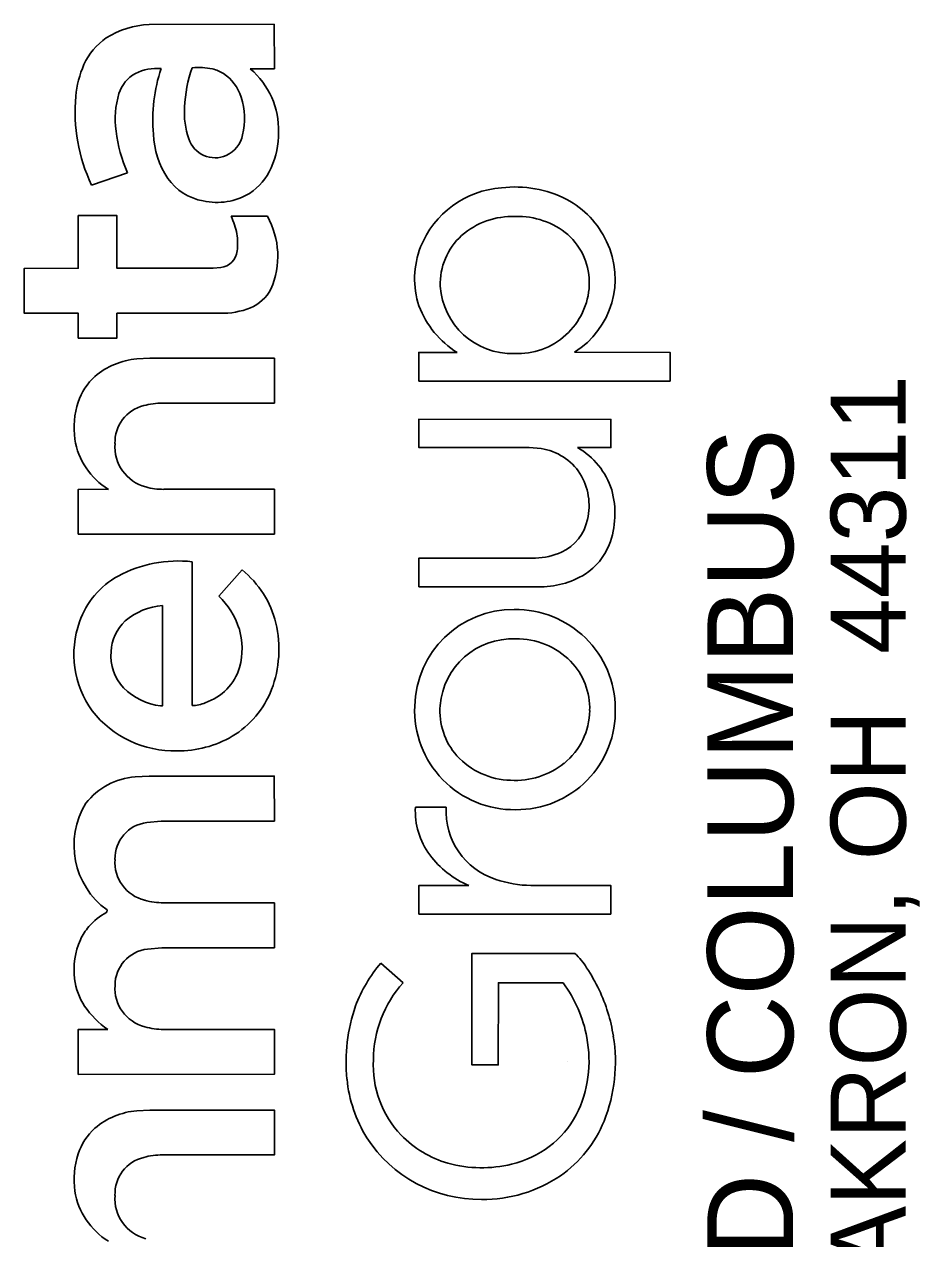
# Model space of a CAD drawing. Extents: x 0 to 34, y 0 to 22.
# Drawn here: x 32.39 to 32.984, y 3.382 to 4.189 of the extents above; entities that cross this region are included whole.
import ezdxf

# ---------------------------------------------------------------- set-up
doc = ezdxf.new("R2010")
doc.units = 0
doc.layers.add('SH_Data', color=7, linetype='Continuous')

msp = doc.modelspace()

# ---------------------------------------------------------------- linework, layer by layer
at = {"layer": 'SH_Data'}
for p, q in [((32.47265, 4.18899), (32.55553, 4.18918)), ((32.55553, 4.18918), (32.55571, 4.15956)), ((32.55571, 4.15956), (32.53971, 4.15956)), ((32.45818, 4.09045), (32.43431, 4.08233)), ((32.42542, 4.02705), (32.42548, 4.06209)), ((32.42548, 4.06209), (32.45108, 4.06209)), ((32.45108, 4.06209), (32.45117, 4.02705)), ((32.52695, 4.06159), (32.5511, 4.06159)), ((32.38964, 4.02701), (32.42542, 4.02705)), ((32.38964, 3.99719), (32.38964, 4.02701)), ((32.45117, 4.02705), (32.51498, 4.02705)), ((32.51498, 4.02705), (32.52005, 4.02749)), ((32.42542, 3.99717), (32.38964, 3.99719)), ((32.42542, 3.98067), (32.42542, 3.99717)), ((32.51969, 3.99718), (32.45108, 3.99715)), ((32.45108, 3.99715), (32.45108, 3.98066)), ((32.45108, 3.98066), (32.42542, 3.98067)), ((32.65152, 3.97113), (32.67709, 3.97115)), ((32.65152, 3.95215), (32.65152, 3.97113)), ((32.75491, 3.97132), (32.81858, 3.97108)), ((32.81858, 3.97108), (32.81843, 3.95215)), ((32.46439, 3.96686), (32.47289, 3.96732)), ((32.47289, 3.96732), (32.55571, 3.96732)), ((32.55571, 3.96732), (32.55571, 3.93753)), ((32.81843, 3.95215), (32.65152, 3.95215)), ((32.55571, 3.93753), (32.4814, 3.93746)), ((32.65152, 3.90801), (32.65153, 3.92672)), ((32.65153, 3.92672), (32.7791, 3.92664)), ((32.7791, 3.92664), (32.77908, 3.90796)), ((32.7249, 3.90796), (32.65152, 3.90801)), ((32.7328, 3.90727), (32.7249, 3.90796)), ((32.77908, 3.90796), (32.75689, 3.90796)), ((32.42542, 3.88016), (32.44552, 3.88021)), ((32.42542, 3.85035), (32.42542, 3.88016)), ((32.48222, 3.88021), (32.55569, 3.88021)), ((32.55569, 3.88021), (32.55571, 3.85045)), ((32.55571, 3.85045), (32.42542, 3.85035)), ((32.65154, 3.83443), (32.72905, 3.8345)), ((32.65165, 3.81543), (32.65154, 3.83443)), ((32.50108, 3.83209), (32.50118, 3.73657)), ((32.51882, 3.80927), (32.53422, 3.82662)), ((32.73073, 3.81543), (32.65165, 3.81543)), ((32.48144, 3.73644), (32.48144, 3.80296)), ((32.48016, 3.73628), (32.48144, 3.73644)), ((32.46329, 3.68915), (32.47259, 3.68968)), ((32.47259, 3.68968), (32.55557, 3.68968)), ((32.55557, 3.68968), (32.55571, 3.65982)), ((32.64932, 3.66907), (32.66978, 3.66907)), ((32.48058, 3.65981), (32.47102, 3.65881)), ((32.55571, 3.65982), (32.48058, 3.65981)), ((32.65152, 3.61699), (32.68476, 3.617)), ((32.65152, 3.598), (32.65152, 3.61699)), ((32.72605, 3.61703), (32.7791, 3.61696)), ((32.7791, 3.61696), (32.77903, 3.598)), ((32.44443, 3.59922), (32.44455, 3.60072)), ((32.48218, 3.60553), (32.55571, 3.60548)), ((32.55571, 3.60548), (32.55571, 3.57568)), ((32.77903, 3.598), (32.65152, 3.598)), ((32.4809, 3.57567), (32.47143, 3.57474)), ((32.55571, 3.57568), (32.4809, 3.57567)), ((32.6868, 3.57185), (32.75516, 3.57192)), ((32.6868, 3.49778), (32.6868, 3.57185)), ((32.62636, 3.56548), (32.64114, 3.55241)), ((32.70448, 3.55241), (32.70432, 3.49775)), ((32.74737, 3.55227), (32.70448, 3.55241)), ((32.42542, 3.49152), (32.42545, 3.52138)), ((32.42545, 3.52138), (32.44515, 3.52138)), ((32.48206, 3.52138), (32.55571, 3.52136)), ((32.55571, 3.52136), (32.55571, 3.49156)), ((32.70432, 3.49775), (32.6868, 3.49778)), ((32.75, 3.5), (32.75, 3.5)), ((32.55571, 3.49156), (32.42542, 3.49152)), ((32.46439, 3.46736), (32.47289, 3.46783)), ((32.47289, 3.46783), (32.55571, 3.46783)), ((32.55571, 3.46783), (32.55571, 3.43804)), ((32.55571, 3.43804), (32.4814, 3.43796))]:
    msp.add_line(p, q, dxfattribs=at)
for points in [[(32.47265, 4.18899), (32.55553, 4.18918), (32.55571, 4.15956)], [(32.55571, 4.15956), (32.53971, 4.15956)], [(32.45818, 4.09045), (32.43431, 4.08233)], [(32.51969, 3.99718), (32.45108, 3.99715), (32.45108, 3.98066), (32.42542, 3.98067), (32.42542, 3.99717), (32.38964, 3.99719), (32.38964, 4.02701), (32.42542, 4.02705), (32.42548, 4.06209), (32.45108, 4.06209), (32.45117, 4.02705), (32.51498, 4.02705), (32.52005, 4.02749)], [(32.52695, 4.06159), (32.5511, 4.06159)], [(32.75491, 3.97132), (32.81858, 3.97108), (32.81843, 3.95215), (32.65152, 3.95215)], [(32.65152, 3.95215), (32.65152, 3.97113), (32.67709, 3.97115)], [(32.46439, 3.96686), (32.47289, 3.96732), (32.55571, 3.96732), (32.55571, 3.93753), (32.4814, 3.93746)], [(32.7328, 3.90727), (32.7249, 3.90796), (32.65152, 3.90801), (32.65153, 3.92672), (32.7791, 3.92664), (32.77908, 3.90796), (32.75689, 3.90796)], [(32.42542, 3.85035), (32.42542, 3.88016), (32.44552, 3.88021)], [(32.48222, 3.88021), (32.55569, 3.88021), (32.55571, 3.85045), (32.42542, 3.85035)], [(32.73073, 3.81543), (32.65165, 3.81543), (32.65154, 3.83443), (32.72905, 3.8345)], [(32.50108, 3.83209), (32.50118, 3.73657)], [(32.51882, 3.80927), (32.53422, 3.82662)], [(32.48016, 3.73628), (32.48144, 3.73644), (32.48144, 3.80296)], [(32.46329, 3.68915), (32.47259, 3.68968), (32.55557, 3.68968), (32.55571, 3.65982), (32.48058, 3.65981), (32.47102, 3.65881)], [(32.64932, 3.66907), (32.66978, 3.66907)], [(32.72605, 3.61703), (32.7791, 3.61696), (32.77903, 3.598), (32.65152, 3.598)], [(32.65152, 3.598), (32.65152, 3.61699), (32.68476, 3.617)], [(32.44443, 3.59922), (32.44455, 3.60072)], [(32.48218, 3.60553), (32.55571, 3.60548), (32.55571, 3.57568), (32.4809, 3.57567), (32.47143, 3.57474)], [(32.74737, 3.55227), (32.70448, 3.55241), (32.70432, 3.49775), (32.6868, 3.49778), (32.6868, 3.57185), (32.75516, 3.57192)], [(32.62636, 3.56548), (32.64114, 3.55241)], [(32.42542, 3.49152), (32.42545, 3.52138), (32.44515, 3.52138)], [(32.48206, 3.52138), (32.55571, 3.52136), (32.55571, 3.49156), (32.42542, 3.49152)], [(32.46439, 3.46736), (32.47289, 3.46783), (32.55571, 3.46783), (32.55571, 3.43804), (32.4814, 3.43796)]]:
    msp.add_lwpolyline(points, dxfattribs=at)
for centre, radius, start, end in [((32.47452, 4.13256), 0.05646, 91.89422, 122.63175), ((32.47452, 4.13256), 0.05646, 91.89422, 122.63175), ((32.46847, 4.14467), 0.04302, 124.53704, 155.65938), ((32.46847, 4.14467), 0.04302, 124.53704, 155.65938), ((32.48824, 4.13612), 0.06457, 155.9764, 175.31491), ((32.48824, 4.13612), 0.06457, 155.9764, 175.31491), ((32.47525, 4.1356), 0.024, 119.42515, 161.66285), ((32.47525, 4.1356), 0.024, 119.42515, 161.66285), ((32.47786, 4.12778), 0.03213, 85.38017, 116.62224), ((32.47786, 4.12778), 0.03213, 85.38017, 116.62224), ((32.58787, 4.12508), 0.1129, 162.08213, 184.52847), ((32.58787, 4.12508), 0.1129, 162.08213, 184.52847), ((32.58013, 4.13131), 0.08411, 159.83657, 178.03621), ((32.58013, 4.13131), 0.08411, 159.83657, 178.03621), ((32.50509, 4.10743), 0.05302, 79.66963, 94.23216), ((32.50509, 4.10743), 0.05302, 79.66963, 94.23216), ((32.50892, 4.13643), 0.02384, 56.89129, 76.21489), ((32.50892, 4.13643), 0.02384, 56.89129, 76.21489), ((32.5052, 4.13184), 0.02973, 17.59837, 55.72819), ((32.5052, 4.13184), 0.02973, 17.59837, 55.72819), ((32.50551, 4.11914), 0.05295, 358.07459, 49.76196), ((32.50551, 4.11914), 0.05295, 358.07459, 49.76196), ((32.53639, 4.13078), 0.113, 174.61011, 205.38987), ((32.53639, 4.13078), 0.113, 174.61011, 205.38987), ((32.50758, 4.12645), 0.05758, 163.13694, 188.16749), ((32.50758, 4.12645), 0.05758, 163.13694, 188.16749), ((32.4916, 4.1264), 0.04435, 345.94084, 18.99188), ((32.4916, 4.1264), 0.04435, 345.94084, 18.99188), ((32.54655, 4.1303), 0.05063, 175.59026, 199.88569), ((32.54655, 4.1303), 0.05063, 175.59026, 199.88569), ((32.54725, 4.12973), 0.09735, 186.75982, 203.79807), ((32.54725, 4.12973), 0.09735, 186.75982, 203.79807), ((32.53279, 4.11874), 0.05752, 182.56764, 213.71437), ((32.53279, 4.11874), 0.05752, 182.56764, 213.71437), ((32.51521, 4.11994), 0.01989, 295.28829, 347.46387), ((32.51521, 4.11994), 0.01989, 295.28829, 347.46387), ((32.50187, 4.11678), 0.05657, 336.01604, 0.59505), ((32.50187, 4.11678), 0.05657, 336.01604, 0.59505), ((32.51642, 4.11886), 0.01841, 198.28436, 293.30806), ((32.51642, 4.11886), 0.01841, 198.28436, 293.30806), ((32.51752, 4.10969), 0.03938, 303.44357, 336.18), ((32.51752, 4.10969), 0.03938, 303.44357, 336.18), ((32.51487, 4.10782), 0.03656, 215.06685, 259.81327), ((32.51487, 4.10782), 0.03656, 215.06685, 259.81327), ((32.51753, 4.1131), 0.04227, 257.52557, 300.88195), ((32.51753, 4.1131), 0.04227, 257.52557, 300.88195), ((32.71081, 4.01825), 0.06243, 93.98662, 158.31194), ((32.71081, 4.01825), 0.06243, 93.98662, 158.31194), ((32.71557, 4.0065), 0.07459, 62.68889, 97.01346), ((32.71557, 4.0065), 0.07459, 62.68889, 97.01346), ((32.72123, 4.01914), 0.06076, 25.06574, 61.96022), ((32.72123, 4.01914), 0.06076, 25.06574, 61.96022), ((32.48625, 4.04199), 0.04518, 10.15449, 25.72303), ((32.48625, 4.04199), 0.04518, 10.15449, 25.72303), ((32.50302, 4.03506), 0.05491, 336.58903, 28.89913), ((32.50302, 4.03506), 0.05491, 336.58903, 28.89913), ((32.71379, 4.01017), 0.05134, 87.89653, 131.18123), ((32.71379, 4.01017), 0.05134, 87.89653, 131.18123), ((32.7175, 4.01023), 0.05127, 49.90886, 92.03625), ((32.7175, 4.01023), 0.05127, 49.90886, 92.03625), ((32.49573, 4.04365), 0.03556, 351.91398, 10.20594), ((32.49573, 4.04365), 0.03556, 351.91398, 10.20594), ((32.7092, 4.01674), 0.04338, 132.32887, 182.09489), ((32.7092, 4.01674), 0.04338, 132.32887, 182.09489), ((32.72154, 4.01733), 0.04327, 358.04871, 47.94467), ((32.72154, 4.01733), 0.04327, 358.04871, 47.94467), ((32.7245, 4.02004), 0.05743, 301.97764, 25.64176), ((32.7245, 4.02004), 0.05743, 301.97764, 25.64176), ((32.51837, 4.04001), 0.01263, 277.61423, 353.79181), ((32.51837, 4.04001), 0.01263, 277.61423, 353.79181), ((32.70695, 4.02016), 0.05815, 158.65601, 198.17101), ((32.70695, 4.02016), 0.05815, 158.65601, 198.17101), ((32.52913, 4.02612), 0.02749, 292.68889, 332.05977), ((32.52913, 4.02612), 0.02749, 292.68889, 332.05977), ((32.71352, 4.01815), 0.04776, 183.59741, 271.7045), ((32.71352, 4.01815), 0.04776, 183.59741, 271.7045), ((32.71717, 4.01801), 0.04766, 267.31494, 357.4019), ((32.71717, 4.01801), 0.04766, 267.31494, 357.4019), ((32.7103, 4.02433), 0.0627, 200.83985, 238.01619), ((32.7103, 4.02433), 0.0627, 200.83985, 238.01619), ((32.52088, 4.04856), 0.05139, 268.67266, 291.52354), ((32.52088, 4.04856), 0.05139, 268.67266, 291.52354), ((32.46871, 3.91716), 0.04988, 94.97056, 130.22484), ((32.46871, 3.91716), 0.04988, 94.97056, 130.22484), ((32.46348, 3.92551), 0.04016, 132.22383, 161.68229), ((32.46348, 3.92551), 0.04016, 132.22383, 161.68229), ((32.47872, 3.92108), 0.05602, 162.27398, 187.79173), ((32.47872, 3.92108), 0.05602, 162.27398, 187.79173), ((32.48108, 3.89145), 0.04601, 89.60515, 105.33026), ((32.48108, 3.89145), 0.04601, 89.60515, 105.33026), ((32.47482, 3.91155), 0.02498, 103.68683, 182.21395), ((32.47482, 3.91155), 0.02498, 103.68683, 182.21395), ((32.47027, 3.9209), 0.04763, 188.96462, 238.69865), ((32.47027, 3.9209), 0.04763, 188.96462, 238.69865), ((32.47735, 3.90846), 0.02757, 175.58441, 255.13816), ((32.47735, 3.90846), 0.02757, 175.58441, 255.13816), ((32.72711, 3.86998), 0.03772, 33.50082, 81.32954), ((32.72711, 3.86998), 0.03772, 33.50082, 81.32954), ((32.73239, 3.86485), 0.04959, 17.62209, 60.38974), ((32.73239, 3.86485), 0.04959, 17.62209, 60.38974), ((32.72414, 3.8695), 0.04048, 346.56179, 31.75389), ((32.72414, 3.8695), 0.04048, 346.56179, 31.75389), ((32.48183, 3.92235), 0.04215, 254.08913, 270.52838), ((32.48183, 3.92235), 0.04215, 254.08913, 270.52838), ((32.72343, 3.86415), 0.05838, 339.16197, 15.61485), ((32.72343, 3.86415), 0.05838, 339.16197, 15.61485), ((32.73371, 3.86616), 0.03042, 294.63214, 348.48625), ((32.73371, 3.86616), 0.03042, 294.63214, 348.48625), ((32.739, 3.85901), 0.04201, 303.10391, 338.15613), ((32.739, 3.85901), 0.04201, 303.10391, 338.15613), ((32.49176, 3.74874), 0.08387, 83.62118, 118.28448), ((32.49176, 3.74874), 0.08387, 83.62118, 118.28448), ((32.72747, 3.88081), 0.04633, 271.95199, 294.08943), ((32.72747, 3.88081), 0.04633, 271.95199, 294.08943), ((32.49399, 3.7763), 0.06443, 13.53275, 51.36266), ((32.49399, 3.7763), 0.06443, 13.53275, 51.36266), ((32.47894, 3.77368), 0.05583, 118.82935, 160.62242), ((32.47894, 3.77368), 0.05583, 118.82935, 160.62242), ((32.7321, 3.87256), 0.05715, 268.62699, 301.47779), ((32.7321, 3.87256), 0.05715, 268.62699, 301.47779), ((32.48033, 3.77018), 0.05485, 19.0387, 45.44322), ((32.48033, 3.77018), 0.05485, 19.0387, 45.44322), ((32.4844, 3.76071), 0.04236, 94.01311, 130.88062), ((32.4844, 3.76071), 0.04236, 94.01311, 130.88062), ((32.71435, 3.73484), 0.06552, 89.48213, 178.77752), ((32.71435, 3.73484), 0.06552, 89.48213, 178.77752), ((32.71582, 3.73414), 0.06623, 0.42265, 90.7613), ((32.71582, 3.73414), 0.06623, 0.42265, 90.7613), ((32.48697, 3.77074), 0.06438, 160.52138, 215.78155), ((32.48697, 3.77074), 0.06438, 160.52138, 215.78155), ((32.47703, 3.7709), 0.02985, 132.98553, 177.1802), ((32.47703, 3.7709), 0.02985, 132.98553, 177.1802), ((32.48724, 3.77433), 0.04701, 344.60723, 17.00675), ((32.48724, 3.77433), 0.04701, 344.60723, 17.00675), ((32.48289, 3.77384), 0.0758, 339.35431, 13.37708), ((32.48289, 3.77384), 0.0758, 339.35431, 13.37708), ((32.71397, 3.73244), 0.04846, 87.68827, 175.01696), ((32.71397, 3.73244), 0.04846, 87.68827, 175.01696), ((32.71659, 3.73036), 0.05052, 44.91202, 90.75914), ((32.71659, 3.73036), 0.05052, 44.91202, 90.75914), ((32.47824, 3.76966), 0.03114, 175.00138, 223.2876), ((32.47824, 3.76966), 0.03114, 175.00138, 223.2876), ((32.49895, 3.77177), 0.03504, 288.01084, 343.55364), ((32.49895, 3.77177), 0.03504, 288.01084, 343.55364), ((32.71955, 3.73452), 0.04549, 358.32279, 43.83486), ((32.71955, 3.73452), 0.04549, 358.32279, 43.83486), ((32.48546, 3.77826), 0.04232, 225.06454, 262.79701), ((32.48546, 3.77826), 0.04232, 225.06454, 262.79701), ((32.49548, 3.76982), 0.0626, 300.94393, 338.73223), ((32.49548, 3.76982), 0.0626, 300.94393, 338.73223), ((32.50129, 3.75678), 0.02021, 269.70042, 294.87295), ((32.50129, 3.75678), 0.02021, 269.70042, 294.87295), ((32.71483, 3.7334), 0.06606, 177.53728, 270.94524), ((32.71483, 3.7334), 0.06606, 177.53728, 270.94524), ((32.71085, 3.73311), 0.0453, 175.51467, 221.42047), ((32.71085, 3.73311), 0.0453, 175.51467, 221.42047), ((32.48908, 3.77516), 0.06872, 217.74341, 271.65606), ((32.48908, 3.77516), 0.06872, 217.74341, 271.65606), ((32.71671, 3.73271), 0.06536, 269.30834, 1.67905), ((32.71671, 3.73271), 0.06536, 269.30834, 1.67905), ((32.71931, 3.73374), 0.04572, 308.90382, 359.30947), ((32.71931, 3.73374), 0.04572, 308.90382, 359.30947), ((32.49204, 3.77702), 0.07055, 269.20529, 300.33566), ((32.49204, 3.77702), 0.07055, 269.20529, 300.33566), ((32.71399, 3.73734), 0.05046, 222.66255, 268.37331), ((32.71399, 3.73734), 0.05046, 222.66255, 268.37331), ((32.71567, 3.73859), 0.05178, 266.55312, 308.67253), ((32.71567, 3.73859), 0.05178, 266.55312, 308.67253), ((32.46638, 3.64404), 0.04521, 93.91118, 142.30723), ((32.46638, 3.64404), 0.04521, 93.91118, 142.30723), ((32.47585, 3.64373), 0.05319, 148.28793, 233.9556), ((32.47585, 3.64373), 0.05319, 148.28793, 233.9556), ((32.69878, 3.66662), 0.04952, 177.16211, 216.28024), ((32.69878, 3.66662), 0.04952, 177.16211, 216.28024), ((32.71735, 3.66638), 0.04764, 176.76988, 252.15044), ((32.71735, 3.66638), 0.04764, 176.76988, 252.15044), ((32.47384, 3.63499), 0.02399, 96.75763, 181.6251), ((32.47384, 3.63499), 0.02399, 96.75763, 181.6251), ((32.47577, 3.63241), 0.02597, 175.81573, 256.16716), ((32.47577, 3.63241), 0.02597, 175.81573, 256.16716), ((32.70975, 3.67555), 0.06366, 216.91526, 246.88619), ((32.70975, 3.67555), 0.06366, 216.91526, 246.88619), ((32.7269, 3.69175), 0.07473, 251.13884, 269.34694), ((32.7269, 3.69175), 0.07473, 251.13884, 269.34694), ((32.4817, 3.65053), 0.04501, 254.34629, 270.61033), ((32.4817, 3.65053), 0.04501, 254.34629, 270.61033), ((32.4638, 3.56267), 0.04137, 117.91625, 139.24296), ((32.4638, 3.56267), 0.04137, 117.91625, 139.24296), ((32.46194, 3.56452), 0.03875, 139.52447, 154.84698), ((32.46194, 3.56452), 0.03875, 139.52447, 154.84698), ((32.47144, 3.5612), 0.04877, 156.06382, 187.3493), ((32.47144, 3.5612), 0.04877, 156.06382, 187.3493), ((32.47421, 3.55056), 0.02434, 96.5532, 179.94902), ((32.47421, 3.55056), 0.02434, 96.5532, 179.94902), ((32.72498, 3.53937), 0.04438, 30.98913, 47.16099), ((32.72498, 3.53937), 0.04438, 30.98913, 47.16099), ((32.70163, 3.50187), 0.09855, 139.79476, 159.13696), ((32.70163, 3.50187), 0.09855, 139.79476, 159.13696), ((32.67091, 3.50018), 0.11106, 25.30315, 33.96179), ((32.67091, 3.50018), 0.11106, 25.30315, 33.96179), ((32.46461, 3.55974), 0.04181, 186.5579, 213.38846), ((32.46461, 3.55974), 0.04181, 186.5579, 213.38846), ((32.47608, 3.54863), 0.02628, 175.722, 255.78627), ((32.47608, 3.54863), 0.02628, 175.722, 255.78627), ((32.69899, 3.50079), 0.07753, 138.25804, 179.70064), ((32.69899, 3.50079), 0.07753, 138.25804, 179.70064), ((32.67889, 3.50099), 0.08556, 10.07509, 36.83189), ((32.67889, 3.50099), 0.08556, 10.07509, 36.83189), ((32.6704, 3.49987), 0.11166, 8.80339, 25.33484), ((32.6704, 3.49987), 0.11166, 8.80339, 25.33484), ((32.47886, 3.57078), 0.0598, 214.70433, 235.68724), ((32.47886, 3.57078), 0.0598, 214.70433, 235.68724), ((32.7187, 3.49968), 0.11536, 161.14379, 185.62812), ((32.7187, 3.49968), 0.11536, 161.14379, 185.62812), ((32.48195, 3.56518), 0.0438, 253.66719, 270.14979), ((32.48195, 3.56518), 0.0438, 253.66719, 270.14979), ((32.68425, 3.50057), 0.08036, 333.46689, 11.03668), ((32.68425, 3.50057), 0.08036, 333.46689, 11.03668), ((32.67564, 3.49977), 0.10649, 338.28866, 9.28548), ((32.67564, 3.49977), 0.10649, 338.28866, 9.28548), ((32.68811, 3.49732), 0.06676, 176.66577, 223.6912), ((32.68811, 3.49732), 0.06676, 176.66577, 223.6912), ((32.69336, 3.49699), 0.08987, 185.50773, 212.01294), ((32.69336, 3.49699), 0.08987, 185.50773, 212.01294), ((32.46871, 3.41767), 0.04988, 94.97056, 130.22484), ((32.46871, 3.41767), 0.04988, 94.97056, 130.22484), ((32.69868, 3.49547), 0.0652, 282.88151, 331.81475), ((32.69868, 3.49547), 0.0652, 282.88151, 331.81475), ((32.46348, 3.42602), 0.04016, 132.22383, 161.68229), ((32.46348, 3.42602), 0.04016, 132.22383, 161.68229), ((32.69835, 3.49168), 0.08241, 305.03061, 337.67573), ((32.69835, 3.49168), 0.08241, 305.03061, 337.67573), ((32.69211, 3.49748), 0.08908, 212.70222, 270.71399), ((32.69211, 3.49748), 0.08908, 212.70222, 270.71399), ((32.69045, 3.50011), 0.07039, 224.02147, 253.88), ((32.69045, 3.50011), 0.07039, 224.02147, 253.88), ((32.47872, 3.42158), 0.05602, 162.27398, 187.79173), ((32.47872, 3.42158), 0.05602, 162.27398, 187.79173), ((32.48108, 3.39196), 0.04601, 89.60515, 105.33026), ((32.48108, 3.39196), 0.04601, 89.60515, 105.33026), ((32.47482, 3.41206), 0.02498, 103.68683, 182.21395), ((32.47482, 3.41206), 0.02498, 103.68683, 182.21395), ((32.69318, 3.51254), 0.08309, 254.45353, 283.9512), ((32.69318, 3.51254), 0.08309, 254.45353, 283.9512), ((32.69429, 3.49979), 0.09138, 269.3273, 304.19632), ((32.69429, 3.49979), 0.09138, 269.3273, 304.19632), ((32.47027, 3.42141), 0.04763, 188.96462, 238.69865), ((32.47027, 3.42141), 0.04763, 188.96462, 238.69865), ((32.47735, 3.40897), 0.02757, 175.58441, 255.13816), ((32.47735, 3.40897), 0.02757, 175.58441, 255.13816)]:
    msp.add_arc(centre, radius, start, end, dxfattribs=at)

# ---------------------------------------------------------------- texts
for s, height, p in [('450 GRANT ST., AKRON, OH  44311', 0.0498462, (32.97489, 2.83738)), ('AKRON / CLEVELAND / COLUMBUS', 0.056969, (32.90012, 2.638))]:
    msp.add_text(s, height=height, rotation=90, dxfattribs=at).set_placement(p)

doc.saveas('drawing.dxf')
